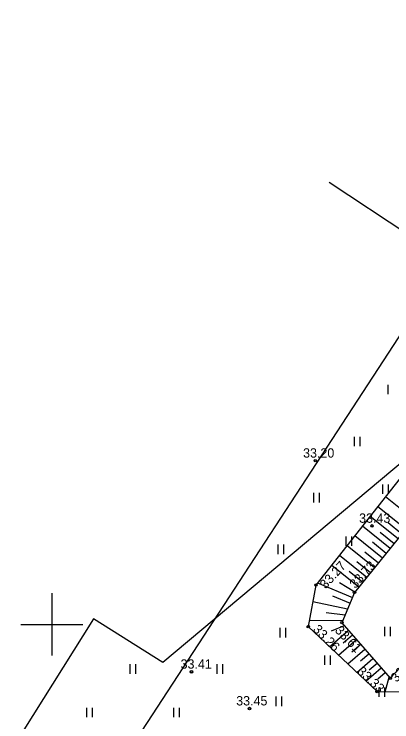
# Model space of a CAD drawing. Extents: x 641898 to 642452, y 6471715 to 6472255.
# Drawn here: x 641997 to 642027.3, y 6472192.2 to 6472249 of the extents above; entities that cross this region are included whole.
import ezdxf

# ---------------------------------------------------------------- set-up
doc = ezdxf.new("R2010")
doc.units = 0
for name, color, linetype in [('HALJASTUS', 7, 'Continuous'), ('KORGUS-EH2000', 7, 'Continuous'), ('MOOTMPUNKT', 7, 'Continuous'), ('MOOTPIIR', 7, 'Continuous'), ('PIIR', 7, 'Continuous'), ('RELJEEF', 7, 'Continuous'), ('VORK', 7, 'Continuous')]:
    doc.layers.add(name, color=color, linetype=linetype)

msp = doc.modelspace()

# ---------------------------------------------------------------- linework, layer by layer
at = {"layer": 'HALJASTUS'}
for p, q in [((642027.006, 6472219.252), (642027.006, 6472218.491)), ((642024.318, 6472215.071), (642024.318, 6472214.31)), ((642024.773, 6472215.071), (642024.773, 6472214.31)), ((642026.588, 6472211.248), (642026.588, 6472210.486)), ((642027.043, 6472211.248), (642027.043, 6472210.486)), ((642021.032, 6472210.561), (642021.032, 6472209.799)), ((642021.487, 6472210.561), (642021.487, 6472209.799)), ((642023.631, 6472207.066), (642023.631, 6472206.305)), ((642024.086, 6472207.066), (642024.086, 6472206.305)), ((642018.165, 6472206.409), (642018.165, 6472205.648)), ((642018.62, 6472206.409), (642018.62, 6472205.648)), ((642018.344, 6472199.718), (642018.344, 6472198.957)), ((642018.799, 6472199.718), (642018.799, 6472198.957)), ((642026.743, 6472199.804), (642026.743, 6472199.043)), ((642027.198, 6472199.804), (642027.198, 6472199.043)), ((642021.928, 6472197.508), (642021.928, 6472196.747)), ((642022.383, 6472197.508), (642022.383, 6472196.747)), ((642006.275, 6472196.795), (642006.275, 6472196.034)), ((642006.73, 6472196.795), (642006.73, 6472196.034)), ((642013.275, 6472196.795), (642013.275, 6472196.034)), ((642013.73, 6472196.795), (642013.73, 6472196.034)), ((642026.289, 6472194.939), (642026.289, 6472194.178)), ((642026.744, 6472194.939), (642026.744, 6472194.178)), ((642018.016, 6472194.193), (642018.016, 6472193.431)), ((642018.471, 6472194.193), (642018.471, 6472193.431)), ((642002.775, 6472193.295), (642002.775, 6472192.534)), ((642003.23, 6472193.295), (642003.23, 6472192.534)), ((642009.775, 6472193.295), (642009.775, 6472192.534)), ((642010.23, 6472193.295), (642010.23, 6472192.534))]:
    msp.add_line(p, q, dxfattribs=at)
at = {"layer": 'KORGUS-EH2000'}
for centre in [(642021.183, 6472213.147), (642025.741, 6472207.912), (642021.238, 6472203.161), (642024.335, 6472202.568), (642023.321, 6472200.131), (642020.615, 6472199.823), (642011.225, 6472196.19), (642027.203, 6472195.68), (642026.15, 6472194.605), (642015.894, 6472193.237)]:
    msp.add_circle(centre, 0.1, dxfattribs=at)
at = {"layer": 'MOOTMPUNKT'}
for centre in [(642021.183, 6472213.147), (642025.741, 6472207.912), (642011.225, 6472196.19), (642015.894, 6472193.237)]:
    msp.add_circle(centre, 0.075, dxfattribs=at)
at = {"layer": 'MOOTPIIR'}
msp.add_lwpolyline([(642014.306, 6472085.384), (642027.67, 6472104.979), (642055.501, 6472084.843), (642081.563, 6472094.262), (642123.938, 6472142.273), (642065.721, 6472244.475), (642008.922, 6472196.948), (642003.347, 6472200.453), (641979.65, 6472162.756), (641979.65, 6472162.756), (641986.045, 6472158.736), (642004.269, 6472142.365), (641987.048, 6472123.488), (641970.482, 6472097.889), (641986.758, 6472084.396)], close=True, dxfattribs=at)
at = {"layer": 'PIIR'}
for p, q in [((642022.295, 6472235.519), (642031.85, 6472229.19)), ((642031.85, 6472229.19), (642000.12, 6472180.55))]:
    msp.add_line(p, q, dxfattribs=at)
at = {"layer": 'RELJEEF'}
for p, q in [((642026.838, 6472210.269), (642029.093, 6472208.443)), ((642026.219, 6472209.483), (642028.463, 6472207.666)), ((642025.6, 6472208.698), (642027.834, 6472206.889)), ((642027.029, 6472208.184), (642028.149, 6472207.277)), ((642024.981, 6472207.912), (642027.205, 6472206.112)), ((642024.362, 6472207.127), (642026.575, 6472205.335)), ((642026.405, 6472207.403), (642027.519, 6472206.5)), ((642025.781, 6472206.621), (642026.89, 6472205.723)), ((642023.743, 6472206.341), (642025.946, 6472204.557)), ((642023.125, 6472205.556), (642025.317, 6472203.78)), ((642025.157, 6472205.84), (642026.261, 6472204.946)), ((642022.506, 6472204.77), (642024.687, 6472203.003)), ((642024.533, 6472205.059), (642025.631, 6472204.169)), ((642023.909, 6472204.277), (642025.002, 6472203.392)), ((642021.368, 6472203.326), (642024.166, 6472202.162)), ((642023.127, 6472203.353), (642024.373, 6472202.615)), ((642022.578, 6472202.281), (642023.974, 6472201.7)), ((642020.989, 6472201.827), (642023.782, 6472201.238)), ((642022.066, 6472200.949), (642023.59, 6472200.777)), ((642020.71, 6472200.331), (642023.398, 6472200.315)), ((642022.492, 6472199.47), (642023.519, 6472199.905)), ((642022.331, 6472198.205), (642023.847, 6472199.528)), ((642023.436, 6472198.506), (642024.176, 6472199.151)), ((642023.062, 6472197.516), (642024.504, 6472198.774)), ((642023.793, 6472196.827), (642025.162, 6472198.02)), ((642024.13, 6472197.784), (642024.833, 6472198.397)), ((642024.825, 6472197.063), (642025.49, 6472197.644)), ((642024.524, 6472196.138), (642025.819, 6472197.267)), ((642025.519, 6472196.341), (642026.148, 6472196.89)), ((642025.255, 6472195.448), (642026.476, 6472196.513)), ((642026.213, 6472195.62), (642026.805, 6472196.136)), ((642026.793, 6472194.592), (642027.134, 6472195.76))]:
    msp.add_line(p, q, dxfattribs=at)
for points in [[(642021.238, 6472203.161), (642020.615, 6472199.823), (642026.15, 6472194.605), (642027.937, 6472194.569), (642041.15, 6472208.366), (642054.15, 6472220.788), (642065.837, 6472231.608), (642070.87, 6472238.181), (642072.479, 6472243.479), (642066.098, 6472249.025), (642059.006, 6472245.135), (642044.784, 6472232.261), (642029.401, 6472213.522), (642021.238, 6472203.161)], [(642027.203, 6472195.68), (642039.818, 6472209.09), (642052.598, 6472221.655), (642065.121, 6472234.45), (642070.097, 6472240.561), (642063.176, 6472246.392), (642050.565, 6472234.28), (642039.282, 6472221.026), (642024.335, 6472202.568), (642023.321, 6472200.131), (642027.203, 6472195.68)]]:
    msp.add_lwpolyline(points, dxfattribs=at)
at = {"layer": 'VORK'}
for p, q in [((642000, 6472202.5), (642000, 6472197.5)), ((641997.5, 6472200), (642002.5, 6472200))]:
    msp.add_line(p, q, dxfattribs=at)

# ---------------------------------------------------------------- texts
at = {"layer": 'KORGUS-EH2000'}
for s, p in [('33.20', (642020.201, 6472213.397)), ('33.43', (642024.706, 6472208.162)), ('33.41', (642010.351, 6472196.44)), ('33.45', (642014.823, 6472193.487))]:
    msp.add_text(s, height=0.75, dxfattribs=at).set_placement(p)
for s, rotation, p in [('33.27', 47.2741, (642022.01, 6472202.795)), ('33.73', 47.2741, (642024.401, 6472202.827)), ('33.26', 314.5908, (642020.937, 6472199.541)), ('33.61', 313.9584, (642022.707, 6472199.465)), ('33.63', 47.2741, (642027.718, 6472195.299)), ('33.33', 316.9306, (642024.486, 6472196.143))]:
    msp.add_text(s, height=0.75, rotation=rotation, dxfattribs=at).set_placement(p)

doc.saveas('drawing.dxf')
